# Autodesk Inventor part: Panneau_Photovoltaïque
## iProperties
Created: 2009-02
Part Number: Panneau_Photovoltaïque
Document SubType Name: Modeling
Designer: Alex_Cyril
Material: Titane
Author: Alex_Cyril
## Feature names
1. Extrusion1
